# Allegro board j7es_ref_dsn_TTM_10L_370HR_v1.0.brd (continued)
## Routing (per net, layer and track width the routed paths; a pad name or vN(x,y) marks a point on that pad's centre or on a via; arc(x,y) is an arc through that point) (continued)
V3V3_DP0:
  vias: v1(129.16,14.94) v1(129.16,14.05) v1(129.16,13.16) v1(129.16,12.27)
VBAT:
  vias: v2(155.96,13.45)
VBAT_A:
  vias: v2(156.84,40.25) v2(156.84,39.11) v2(156.84,37.96) v2(156.84,36.82) v2(157.86,36.82) v2(158.88,36.82) v2(159.89,36.82) v2(160.78,36.82) v2(161.42,37.71) v2(161.8,38.85)
VBAT_F: length 2.3
  TOP w0.305: R1037.1 165.48,49.14 164.92,48.58 D1008.2
  vias: v2(164.47,73.14) v2(164.47,72.25) v2(164.47,71.36) v2(164.47,70.47) v2(167.89,70.47) v2(168.78,70.47) v2(169.67,70.47) v2(170.56,70.47)
VBAT_PM: length 15.6
  TOP w0.508: 159.51,16.26 159.51,17.13 ; 159.51,17.13 160.05,17.13 ; 159.51,17.13 158.98,17.13 ; 159.51,17.13 159.51,18.01 ; 155.33,17.64 C1023.1 ; C1023.1 156.83,17.64 ; C1023.1 156.08,17.02 ; R1012.2 158.12,15.78 ; R1012.2 156.35,15.15 ; R1012.2 159.88,15.15 ; 160.78,16.26 Q1002.3 ; Q1002.3 160.25,17.13 ; Q1002.3 160.78,18.01 ; Q1002.1 158.24,18.01 ; Q1002.1 158.78,17.13 ; Q1002.1 157.71,17.13 ; Q1002.1 158.24,16.26 ; 167.19,18.08 U1006.4 166.84,17.02
  vias: v2(149.22,16.5) v2(149.22,15.48) v2(149.22,14.47) v2(149.73,13.58) v2(150.62,13.58) v2(151.51,13.58) v2(152.4,13.58) v2(153.29,13.58) v2(153.8,16.5) v2(153.8,15.48) v2(153.8,14.47)
VBAT_SYS: length 11.5
  TOP w0.203: U1007.15 v2(192.28,98.42)
  TOP w0.305: v2(192.15,96.26) 191.64,96.26 191.21,96.69 C1028.1 191.21,96.84 191.64,97.27 v2(192.15,97.27) ; 36.2,29.58 v2(36.2,30.98)
  L4-SIGNAL w0.305: v2(192.15,97.27) 192.28,97.4 v2(192.28,98.42)
  BOTTOM w0.305: C2115.1 v2(36.2,30.98) RJ2008.1
  BOTTOM w0.508: v2(199.64,102.22) 199.52,102.1 R1142.2
  vias: v2(183.77,98.8) v2(183.77,97.91) v2(184.53,98.8) v2(184.53,97.91) v2(185.29,98.8) v2(185.29,97.91) v2(196.22,96.26)
VBUS_USBC_CONN: length 1.5
  TOP w0.305: v2(177.29,138.04) R1000.1
  BOTTOM w0.229: R171.1 v2(147.32,130.77)
  vias: v2(171.83,140.71) v2(171.83,139.82) v2(172.21,138.8) v2(172.21,137.78) v2(172.21,136.51) v2(172.21,135.37)
VCC_12V0:
  vias: v1(98.23,36.91) v1(98.23,35.99) v1(98.23,35.08) v1(99.15,36.91) v1(99.15,35.99) v1(99.15,35.08) v1(100.09,36.91) v1(100.09,35.99) v1(100.09,35.08)
VCC_12V_DSI0:
  vias: v1(99.69,6.63) v1(99.69,5.61) v1(99.69,4.6) v1(100.71,6.63) v1(100.71,5.61) v1(100.71,4.6) v1(101.6,6.63) v1(101.6,5.61) v1(101.6,4.6)
VCC_LM5141: length 7.7
  TOP w0.305: D1004.2 184.61,101.03 185.6,102.02 C1043.1 187.78,102.02 188.72,101.09 U1007.10
VCC_LM5175: length 24.1
  TOP w0.203: v2(168.4,48.63) 168.4,48.38 R1040.2
  TOP w0.305: U1008.23 172.76,61.5 v2(172.97,61.71) ; D1005.2 173.02,61.76 v2(172.97,61.71) ; v2(172.97,61.71) C1040.1 170.38,61.71 D1007.2
  BOTTOM w0.305: v2(172.97,61.71) 172.97,58.66 171.07,56.76 171.07,52.06 168.4,49.39 v2(168.4,48.63)
VCCA_3V3: length 15.8
  TOP w0.305: v1(81.28,104.67) U29.4 ; 126.49,99.68 126.53,99.65 U27.17 ; U29.10 v1(79.73,107.67) ; U29.54 78.7,101.63 78.74,101.59 ; U27.12 v1(129.07,100.7) ; U27.26 126.53,95.15 126.49,95.11 ; v1(133.07,102.22) U27.4 ; 78.74,111.24 78.7,111.21 U29.17 ; U29.35 71.68,106.67 ; U29.8 v1(79.73,106.67) ; U27.35 131.07,92.63 ; U27.8 v1(131.07,100.68) ; 74.17,101.59 74.2,101.63 U29.45 ; U27.54 136.11,99.65 136.14,99.68 ; 74.17,111.24 74.2,111.21 U29.26 ; U27.10 v1(130.07,100.68) ; U27.45 136.11,95.15 136.14,95.11 ; U29.12 v1(79.76,108.67)
  BOTTOM w0.305: v1(81.28,104.67) 81,104.38 C532.1 ; C481.1 133.35,101.94 v1(133.07,102.22)
  vias: v2(66.04,118.35) v2(66.04,117.34) v2(67.06,118.35) v2(67.06,117.34) v2(68.07,118.35) v2(68.07,117.34) v2(69.38,106.62) v2(69.38,105.98) v2(70.32,106.62) v2(70.32,105.98) v2(73.46,113.49) v2(73.46,112.55) v2(73.46,100.28) v2(73.46,99.34) v2(74.09,113.49) v2(74.09,112.55) v2(74.09,100.28) v2(74.09,99.34) v2(78.81,113.49) v2(78.81,112.55) v2(78.81,100.28) v2(78.81,99.34) v2(79.45,113.49) v2(79.45,112.55) v2(79.45,100.28) v2(79.45,99.34) v2(84.96,118.61) v2(84.96,117.59) v2(85.69,102.29) v2(85.98,118.61) v2(85.98,117.59) v2(86.21,101.69) v2(86.74,101.17) v2(87,118.61) v2(87,117.59) v2(87.95,106.95) v2(88.49,106.42) v2(89.01,105.86) v2(124.24,100.39) v2(124.24,99.76) v2(124.24,95.04) v2(124.24,94.4) v2(125.18,100.39) v2(125.18,99.76) v2(125.18,95.04) v2(125.18,94.4) v2(131.12,91.26) v2(131.12,90.32) v2(131.75,91.26) v2(131.75,90.32) v2(137.45,100.39) v2(137.45,99.76) v2(137.45,95.04) v2(137.45,94.4) v2(138.39,100.39) v2(138.39,99.76) v2(138.39,95.04) v2(138.39,94.4) v2(153.29,103.24) v2(153.29,101.97) v2(153.67,103.88) v2(153.67,102.61) v2(153.67,101.34) v2(154.05,103.24) v2(154.05,101.97) v2(154.43,103.88) v2(154.43,102.61) v2(154.43,101.34) v2(154.81,103.24) v2(154.81,101.97) v2(155.19,103.88) v2(155.19,102.61) v2(155.19,101.34) v2(155.57,103.24) v2(155.57,101.97) v2(155.96,103.88) v2(155.96,102.61) v2(155.96,101.34)
VDD1_LPDDR4_1V8: length 8.2
  TOP w0.305: v1(122.13,70.36) 122.53,70.03 U11.U12 ; U11.U1 131.33,70.03 v1(131.73,69.71) ; U11.G9 v1(124.53,63.86) ; C514.1 127.99,103.42 128.57,102.84 v1(128.57,102.1) U27.13 ; U11.T9 124.93,69.38 v1(124.53,69.06) ; U11.T4 128.93,69.38 v1(129.33,69.06) ; U11.F1 v1(131.73,63.21) ; U11.F12 v1(122.13,62.56) ; U11.G4 v1(128.53,63.86)
  BOTTOM w0.305: C341.1 121.94,70.17 v1(122.13,70.36) ; C345.1 131.81,69.79 v1(131.73,69.71)
  vias: v1(123.27,57.01) v1(125.17,76.06) v1(127.71,57.01) v1(128.35,76.06) v1(131.52,74.54) v1(134.03,58.28) v1(134.24,73.84)
VDD18_DSI: length 15
  TOP w0.305: v1(111.51,15.23) R3066.1 110.98,15.86 v1(109.56,17.28) ; R3065.1 v1(103.89,15.74)
  L2-SIGNAL w0.305: v1(109.56,17.28) 106.11,17.28 104.56,15.74 v1(103.89,15.74)
  BOTTOM w0.229: R3066.1 v1(111.51,15.23)
  BOTTOM w0.305: 108.83,17.28 v1(109.56,17.28) ; 108.83,17.28 U3019.24 ; 108.83,17.28 C3111.1 ; v1(110.94,29.76) 110.94,29.03 ; 110.94,29.03 C3100.1 ; 110.94,29.03 110.94,28.54 110.83,28.44 U3019.61
  vias: v1(112.01,34.28) v1(113.16,35.29) v1(114.81,34.66)
VDD_1P0: length 7
  TOP w0.305: C2086.1 44.78,29.25 C2087.1 ; C2086.1 46.23,28.4 46.35,28.27 R2059.2 R2058.2 ; C2086.1 46.43,29.45 L2017.2
VDD_CORE_0V8: length 100.9
  TOP w0.305: U9.K17 97.05,67.75 v1(96.65,67.35) ; U9.K11 v1(102.25,67.35) ; v1(97.45,73.75) 97.85,73.35 U9.U16 ; v1(98.25,72.15) 98.65,72.55 U9.T15 ; U9.N18 96.25,70.15 v1(95.85,69.75) ; v1(103.85,72.15) 103.45,72.55 U9.T9 ; v1(99.05,73.75) 99.45,73.35 U9.U14 ; 94.41,88.19 C66.3 ; U9.K15 98.65,67.75 v1(98.25,67.35) ; U9.V15 98.65,74.15 v1(98.25,74.55) ; U9.V20 94.65,74.15 v1(94.25,74.55) ; U9.L10 v1(103.05,68.15) ; U9.L18 96.25,68.55 v1(95.85,68.15) ; U9.T17 97.05,72.55 v1(96.65,72.15) ; U9.R16 97.85,71.75 v1(97.45,71.35) ; v1(94.25,71.35) 94.65,71.75 U9.R20 ; v1(98.25,70.55) 98.65,70.95 U9.P15 ; v1(99.85,71.35) 99.45,71.75 U9.R14 ; U9.W14 99.45,74.95 v1(99.05,75.35) ; U9.K9 v1(103.85,67.35) ; v2(75.92,111.47) 75.92,111.39 76.2,111.11 U29.22 ; U9.L16 97.85,68.55 v1(97.45,68.15) ; U9.R18 96.25,71.75 v1(95.85,71.35) ; U9.N16 97.85,70.15 v1(97.45,69.75) ; U9.P17 97.05,70.95 v1(96.65,70.55) ; U9.J10 v1(103.05,66.55) ; U9.P13 100.25,70.95 v1(100.65,70.55) ; U9.N14 v1(99.85,69.75) ; U9.M15 98.65,69.35 v1(98.25,68.95) ; U9.K13 v1(100.65,67.35) ; U9.V17 v1(96.65,74.55) ; U9.U18 v1(95.85,73.75)
  L6-PWR/GND w0.152: v1(94.25,71.35) 93.85,70.95 93.85,70.35 93.65,70.14 86.87,70.14 86.08,70.93 84.83,70.93 81.63,74.13 77.11,74.13 73.63,77.61 73.63,97.93 72.42,99.15 72.42,103.34 72.42,103.34 72.42,107.88 72.42,107.88 72.42,108.45 72.42,108.45 72.42,109.36 73.81,110.76 75.34,110.76 75.62,111.04 75.62,111.16 v2(75.92,111.47)
  BOTTOM w0.152: C318.1 103.88,72.13 v1(103.85,72.15)
  BOTTOM w0.203: C292.1 99.05,75.35 v1(99.05,75.35) ; C336.1 96.55,70.41 96.25,70.11 96.22,70.11 v1(95.85,69.75) ; v1(98.25,68.95) 98.25,68.97 97.87,69.35 97.81,69.35 97.51,69.65 C342.1 ; v1(96.65,70.55) 95.99,71.21 C330.1 ; v1(95.85,71.35) 96.15,71.65 96.15,71.67 96.55,72.06 C322.1 ; v1(96.65,67.35) 96.3,67.7 96.29,67.7 95.99,68 C361.1 ; C335.1 98.07,70.37 v1(97.45,69.75)
  BOTTOM w0.305: v1(97.45,68.15) 97.84,68.54 97.92,68.54 98.2,68.82 C353.1 ; C340.1 C352.1 ; v1(97.45,69.75) v1(96.65,70.55) 96.65,70.55 v1(97.45,71.35) 97.45,71.29 97.79,70.95 97.84,70.95 v1(98.25,70.55) ; C328.1 100.04,71.35 v1(99.85,71.35) v1(99.85,72.15) ; v1(102.25,67.35) v1(103.05,68.15) v1(103.85,67.35) ; v1(95.85,73.75) v1(96.65,74.55) 96.67,74.55 97.17,74.04 97.17,74.02 v1(97.45,73.75) v1(98.25,74.55) 98.59,74.89 98.59,74.89 v1(99.05,75.35) ; v1(103.05,66.55) 103.05,66.66 103.28,66.89 103.38,66.89 103.66,67.17 C364.1
  vias: v1(77.43,85.59) v1(77.43,81.78) v1(79.03,85.59) v1(79.03,81.78) v1(81.03,78.86) v1(81.03,75.43) v1(81.99,85.59) v1(81.99,81.78) v1(82.03,78.86) v1(82.03,75.43) v1(83.36,78.91) v1(83.36,75.43) v1(84.07,88.3) v1(84.36,75.43) v1(84.41,85.61) v1(84.48,78.91) v1(84.53,81.78) v1(85.34,88.3) v1(85.98,93.37) v1(85.98,91.77) v1(86.61,88.3) v1(87.88,88.3) v1(88.52,93.37) v1(88.52,91.77) v1(90.88,91.42) v1(90.88,90.37) v1(90.93,89.26) v1(90.93,88.26) v1(93.22,84.62) v1(94.35,91.42) v1(94.37,90.41) v1(94.34,89.29) v1(94.36,88.25) v2(65.79,93.72) v2(66.67,93.72) v2(68.2,93.72) v2(69.22,93.72) v2(71.5,117.46) v2(71.5,116.32) v2(71.5,115.18) v2(71.5,97.65) v2(71.5,96.51) v2(71.5,95.37) v2(72.39,117.46) v2(72.39,116.32) v2(72.39,115.18) v2(72.39,97.65) v2(72.39,96.51) v2(72.39,95.37) v2(75.31,119.62) v2(75.31,118.61) v2(75.31,94.22) v2(75.31,93.21) v2(76.45,119.62) v2(76.45,118.61) v2(76.45,94.22) v2(76.45,93.21) v2(77.6,119.62) v2(77.6,118.61) v2(77.6,94.22) v2(77.6,93.21) v2(80.52,117.46) v2(80.52,116.32) v2(80.52,115.18) v2(80.52,97.65) v2(80.52,96.51) v2(80.52,95.37) v2(81.41,117.46) v2(81.41,116.32) v2(81.41,115.18) v2(81.41,97.65) v2(81.41,96.51) v2(81.41,95.37) v2(84.71,94.86) v2(85.72,94.86) v2(87.12,94.86) v2(88.14,94.86) v2(93.65,97.65) v2(93.65,96.89) v2(93.65,96.26) v2(96.39,42.53) v2(103.63,94.22) v2(107.82,42.53)
VDD_CORE_RAM_0V85: length 2.3
  TOP w0.305: U9.V16 97.85,74.15 v1(97.45,74.55) ; v1(100.65,74.55) 100.25,74.15 U9.V13 ; U9.L14 v1(99.85,68.15) ; U9.W19 v1(95.05,75.35)
  vias: v2(72.52,78.35) v2(77.34,79.62)
VDD_CPU_AVS: length 85.9
  TOP w0.305: U9.N10 102.65,70.14 v1(103.05,69.74) ; U9.N10 v1(102.25,70.55) 101.85,70.95 U9.P11 101.85,70.94 v1(102.25,71.34) ; U9.N10 v1(102.25,69.74) ; v1(103.05,71.35) 102.65,71.75 U9.R10 102.65,71.74 v1(102.25,72.14) ; v1(101.45,72.14) 101.05,71.75 U9.R12 101.05,71.74 v1(100.65,72.14) ; U9.V9 103.45,74.15 v1(103.85,74.55) ; U9.U10 102.65,73.35 v1(103.05,73.75) ; v1(102.25,74.55) 101.85,74.15 U9.V11 ; U27.22 126.62,97.15 126.34,96.87 v2(126.26,96.87) ; v1(103.05,75.35) 102.65,74.95 U9.W10
  L4-SIGNAL w0.152: v2(126.26,96.87) 126.77,96.87 127.25,96.38 127.25,94.22 128.02,93.46 136.02,93.46 137.03,92.45 137.03,87.54 135.2,85.71 135.2,79.53 132.83,77.16 111.84,77.16 110.42,75.74 109.29,75.74 109.29,75.74 108.49,75.74 108.26,75.51 108.26,75.23 108.25,75.22 108.25,75.18 108.02,74.95 107.98,74.95 107.97,74.94 107.69,74.94 107.46,74.71 107.46,74.43 107.46,74.43 107.46,74.35 107.26,74.16 106.88,74.16 106.65,73.93 106.65,73.37 106.55,73.27 104.44,73.27 104.25,73.47 104.25,74.16 v1(103.85,74.55)
  BOTTOM w0.305: v1(103.05,71.35) 102.26,71.35 v1(102.25,71.34) ; 102.23,73.73 102.23,73.68 102.31,73.75 v1(103.05,73.75) ; C69.3 100.66,72.15 ; 100.66,72.15 v1(100.65,72.14) ; 100.66,72.15 100.74,72.23 C351.1 102.17,72.23 v1(102.25,72.14) ; C69.1 100.66,73.75 v1(100.66,73.75) v1(101.45,73.75) 101.47,73.76 102.24,73.76 v1(102.25,73.75) 102.25,74.46 102.23,74.54 C304.1 ; v1(102.25,72.14) 102.52,72.4 C68.1 ; v1(102.25,72.14) 102.25,72.14 v1(102.25,71.34) ; v1(102.25,71.34) v1(102.25,70.55) v1(102.25,69.74) v1(103.05,69.74) ; C68.3 103.22,73.68 C308.1 ; v1(103.85,74.55) 103.17,73.87 C308.1 ; 103.15,73.75 C308.1 ; C298.1 103.75,74.64 103.12,75.27 C294.1 102.67,74.95 102.62,74.95 102.25,74.59 v1(102.25,74.55)
  vias: v1(107.24,88.3) v1(109.02,88.3) v1(110.87,88.3) v1(112.65,89.4) v1(112.65,88.15) v1(115.36,86.22) v1(115.36,84.32) v1(115.36,82.41) v1(117.35,86.22) v1(117.35,84.32) v1(118.36,86.22) v1(118.36,84.32) v1(119.47,86.22) v1(119.47,84.32) v1(119.47,82.41) v1(121.07,86.22) v1(121.07,84.32) v1(121.07,82.41) v1(122.26,86.22) v1(123.86,86.22) v2(118.62,104.38) v2(119.63,104.38) v2(120.27,102.35) v2(120.27,101.46) v2(120.27,93.33) v2(120.27,92.45) v2(121.03,104.38) v2(121.41,102.35) v2(121.41,101.46) v2(121.41,93.33) v2(121.41,92.45) v2(122.05,104.38) v2(122.55,102.35) v2(122.55,101.46) v2(122.55,93.33) v2(122.55,92.45) v2(123.88,83.2) v2(124.89,83.2) v2(126.36,83.23) v2(127.38,83.23)
VDD_CPU_RAM_0V85: length 1.1
  TOP w0.305: U9.L11 v1(102.25,68.15) ; v1(101.45,75.35) 101.05,74.95 U9.W12
  vias: v2(90.94,103.75) v2(92.2,99.3)
VDD_DDR_1V1: length 84.7
  TOP w0.089: 126.06,69.71 124.45,69.71 U11.U10 123.8,69.71 123.06,69.71
  TOP w0.102: U11.F8 125.4,63.21 124.45,63.21 U11.F10
  TOP w0.203: U11.H12 122.29,63.95 121.95,63.95 121.68,64.22 121.68,64.72 v1(122.1,65.14)
  TOP w0.229: U9.T1 109.86,72.54 ; U11.F10 123.83,63.19 123.83,63.24 ; v1(136.14,97.65) 136.14,97.65 U27.50
  TOP w0.305: U11.B10 124.05,60.28 123.7,59.93 ; U11.N10 124.13,67.43 v1(124.53,67.76) ; U11.F3 v1(130.13,62.56) ; U9.N8 v1(104.65,69.75) ; U11.R12 122.53,68.73 v1(122.13,68.41) ; U11.D8 125.73,61.58 126.11,61.2 ; U9.R6 105.85,71.75 v1(106.25,71.35) ; U11.F8 v1(126.13,62.56) ; v1(129.33,59.96) 128.93,59.63 U11.A4 ; U9.G8 104.25,65.35 U9.G8 ; U9.G8 v1(104.65,64.95) ; U11.W1 132.54,71.33 v1(132.59,71.28) ; U9.P7 105.05,70.95 v1(105.45,70.55) ; v1(127.73,69.71) 128.13,70.03 U11.U5 ; U9.J6 105.85,66.95 v1(106.25,66.55) ; U11.N3 129.73,67.43 v1(129.33,67.76) ; 122.3,61.33 122.53,61.56 U11.D12 122.53,61.61 122.3,61.84 ; v1(127.73,69.06) 128.13,68.73 U11.R5 ; 109.86,72.55 U9.T1 109.85,72.55 ; v1(122.65,66.56) 122.53,66.69 U11.N12 ; U11.W5 127.67,71.33 ; v1(105.45,68.95) 105.05,69.35 U9.M7 ; v1(131.73,65.81) U11.K1 ; 127.76,59.93 128.11,60.28 U11.B5 ; U11.H1 v1(131.73,64.51) ; U11.B3 v1(130.13,60.61) ; U11.K12 122.12,65.15 122.1,65.14 v1(122.1,65.14) ; U11.H5 v1(127.73,63.86) ; U11.AB9 124.93,73.28 125.18,73.54 v1(125.18,73.76) ; U9.K7 v1(105.45,67.35) ; U9.R8 104.25,71.75 v1(104.65,71.35) ; 127.76,73.01 128.13,72.65 U11.AA5 ; v1(130.13,72.31) 129.73,72.63 U11.AA3 ; U9.L8 v1(104.65,68.15) ; v1(105.45,72.15) 105.05,72.55 U9.T7 ; U11.B8 126.01,60.57 ; U11.R1 131.33,68.73 v1(131.73,68.41) ; U11.AA8 126.11,73.01 ; U11.W8 126.21,71.33 ; U11.F5 v1(127.73,62.56) ; U11.U8 125.73,70.03 v1(126.13,70.36) ; U9.A1 v1(110.25,60.14) ; v1(104.65,66.55) 104.25,66.95 U9.J8 ; U11.W12 121.95,71.33 ; v1(125.33,59.96) 125.32,59.96 124.94,59.64 124.93,59.63 U11.A9 ; 132.54,61.58 v1(132.59,61.54) ; U11.H8 v1(126.13,63.86) ; v1(126.13,69.06) 125.73,68.73 U11.R8 ; v1(131.73,67.11) 131.33,67.43 U11.N1 ; v1(130.13,70.36) 129.73,70.03 U11.U3 ; 131.57,61.33 131.33,61.57 U11.D1 131.33,61.59 131.57,61.84 ; v1(124.53,65.16) U11.K10 ; U11.AB4 v1(128.93,73.82) ; U11.AA10 123.75,73.01 ; 109.86,72.54 v1(110.25,72.15) ; U9.M9 v1(103.85,68.95) ; v1(129.33,65.16) U11.K3 ; U9.H7 v1(105.45,65.75) ; U11.D5 127.64,61.58
  L4-SIGNAL w0.152: v1(136.14,97.65) 135.64,97.65 135.38,97.4 135.38,95.11 137.69,92.8 137.69,87.38 135.79,85.47 135.79,79.25 133.35,76.81 133.35,70.03 v1(131.73,68.41)
  BOTTOM w0.229: v1(110.25,72.15) 110.28,72.13 C317.1 ; R180.1 v1(120.69,88.35)
  BOTTOM w0.305: v1(110.25,60.14) 110.54,60.43 110.83,60.72 110.92,60.72 C390.1 ; v1(125.18,73.76) 125.27,73.85 C303.1 ; R242.1 127.89,58.64 126.75,58.64 R243.1 v1(126.75,58) ; v1(132.59,66.92) 132.67,67 C374.1 ; C384.1 122.02,65.22 v1(122.1,65.14) ; v1(128.93,73.82) 128.98,73.88 C302.1 ; R232.1 119.29,67.57 119.53,67.81 119.53,68.52 119.63,68.62 v2(119.91,68.9) ; C393.1 125.05,59.68 v1(125.33,59.96) ; v1(129.33,59.96) 129.33,59.95 C392.1
  vias: v1(112.66,58.03) v1(113.66,58.03) v1(114.17,54.97) v1(114.17,53.96) v1(115.36,70.6) v1(115.36,68.06) v1(115.36,61.71) v1(115.32,58.03) v1(115.95,54.97) v1(115.95,53.96) v1(116.33,58.03) v1(117.73,55.27) v1(117.73,53.67) v1(121.46,55.49) v1(122.6,77.97) v1(123.01,76.06) v1(123.62,55.49) v1(124.64,77.97) v1(125.55,57.01) v1(125.78,55.49) v1(126.67,77.97) v1(126.93,63.16) v1(128.06,55.49) v1(128.7,77.97) v1(130.13,57.01) v1(130.35,55.49) v1(131.25,66.33) v1(131.52,76.06) v1(132.13,59.35) v1(132.79,58.28) v1(132.84,56.75) v1(132.84,55.74) v1(134.24,71.05) v1(134.75,56.75) v1(134.75,55.74) v1(134.87,67) v1(134.87,63.82) v1(134.87,60.65) v1(135.38,75.93) v1(135.38,74.92) v1(136.09,68.91) v1(136.52,60.65) v1(136.65,58.45) v1(136.65,56.85) v1(137.29,74.02) v1(137.29,73.01) v1(137.29,70.93) v1(137.26,61.85) v1(139.06,72.38) v1(139.06,71.36) v1(139.06,70.35) v1(140.21,72.38) v1(140.21,71.36) v1(140.21,70.35) v2(140.08,102.35) v2(140.08,101.46) v2(141.22,102.35) v2(141.22,101.46) v2(142.37,102.35) v2(142.37,101.46)
VDD_DSI_OSC: length 6.4
  BOTTOM w0.229: 100.73,17.93 C3108.2 100.76,18.45 100.97,18.66 U3020.4
  BOTTOM w0.305: 100.71,17.3 100.73,17.32 ; 100.73,17.93 99.82,17.93 99.42,18.34 U3020.1
  BOTTOM w0.381: 100.71,17.3 100.46,17.04 FL3026.3 ; 100.73,17.32 100.73,17.93
VDD_IO_1V8: length 35.9
  TOP w0.305: U9.AA8 104.25,76.55 v1(104.65,76.95) 104.66,76.95 U9.AB7 105.05,77.35 v1(105.45,77.75) ; U1017.H8 v2(154.66,82.2) ; U1017.P8 v2(147.66,82.2) ; v1(120.36,34.57) 119.63,34.57 v1(119.63,33.88) ; C544.1 81.85,107.05 81.73,107.17 v1(81.15,107.17) U29.9 ; U1017.L4 v2(150.66,87.21) ; U1017.P3 v2(147.66,88.21) ; U1017.L2 v2(150.66,89.21) ; C260.1 v1(102.13,92.95) ; U1017.L7 v2(150.66,83.21) ; U9.Y7 105.05,75.75 v1(105.45,76.15) ; U1017.H3 v2(154.66,88.21) ; U1017.L9 v2(150.66,81.2)
  L6-PWR/GND w0.305: v2(108.58,97.65) v2(108.58,96.76) v2(108.58,95.87) 106.93,95.87 104.01,92.95 v1(102.13,92.95)
  BOTTOM w0.305: R1198.1 R1191.1 150.62,81.17 v2(150.66,81.2) ; v2(147.66,82.2) 147.45,82.41 C1249.1 ; R1189.1 v2(152.65,88.25) R1188.1 ; 151.38,85.97 151.38,86.48 v2(150.66,87.21) ; v2(146.43,83.43) 146.1,83.43 145.8,83.73 145.8,84.19 ; v2(150.66,89.21) 149.84,90.03 R1197.1 ; v2(150.66,83.21) 150.5,83.05 R1196.1 ; v2(147.66,88.21) 147.7,88.17 R1201.1 ; v2(154.66,82.2) 154.45,82.41 C1242.1 ; v2(152.65,84.19) 152.53,84.06 R1190.1 ; R1200.1 v2(148.72,84.19)
  vias: v1(102.13,91.68) v1(102.11,90.41) v1(102.11,89.14)
VDD_IO_3V3: length 59.8
  TOP w0.305: U9.AC20 94.65,78.15 v1(94.25,78.55) ; R1001.2 v2(168.02,134.23) ; v1(92.65,73.75) 93.05,73.35 U9.U22 ; U9.AC19 95.46,78.15 v1(95.06,78.55) ; R79.1 v2(40.89,71.87) ; U1017.F7 v2(156.66,83.21) ; R23.1 v2(142.88,82.92) ; U9.AA21 v1(93.45,76.95) ; U1017.F9 v2(156.66,81.2) ; R81.1 v2(40.89,74.41) ; v2(114.73,116.65) R20.1 R25.1 ; v1(96.65,78.55) 97.05,78.15 U9.AC17 ; 36.2,35.17 v2(36.2,36.57) ; R38.1 R37.1 v2(104.98,25.59) ; v1(94.26,73.75) 94.66,73.35 U9.U20 ; U9.AA17 97.05,76.55 v1(96.65,76.95) ; R43.2 v2(55.45,89.73) ; U9.W22 93.05,74.95 v1(92.65,75.35) ; U9.AA20 94.66,76.55 v1(94.26,76.95) ; v1(97.45,77.75) 97.85,77.35 U9.AB16 ; C1209.2 v2(137.29,147.44) U1011.8 ; v1(104.65,73.75) 104.25,73.35 U9.U8 ; RJ1000.1 v2(176.47,134.36) ; v2(49.4,34.79) R2020.1 R2021.1 ; C2084.1 v2(55.75,31.36) ; R27.1 v2(148.46,76.7) ; R86.1 v2(55.63,70.09) ; U1017.F8 v2(156.66,82.2) ; U9.V21 93.86,74.15 v1(93.46,74.55) ; R1002.2 v2(168.02,133.09) ; U1017.F5 v2(156.66,86.21) ; L2004.2 v2(43.69,33.14) ; U9.V7 105.05,74.15 v1(105.45,74.55) ; U1017.F2 v2(156.66,89.21) ; R66.1 R54.1 v2(156.08,76.82) ; U1017.F6 v2(156.66,84.21) ; U1002.9 158.81,126.16 v2(158.62,125.97) ; U2023.3 v2(52.2,29.07) ; U9.Y22 93.05,75.75 v1(92.65,76.15) ; R3061.2 v2(128.23,19.51) ; U2023.4 v2(54.23,29.07) ; U9.AA19 v1(95.05,76.95) ; U9.AB18 96.25,77.35 v1(95.85,77.75) ; L2008.1 v2(38.35,48.38) ; U2023.6 v2(54.23,31.36) ; U1017.F3 v2(156.66,88.21) ; U1017.F4 v2(156.66,87.21)
  BOTTOM w0.305: v2(156.66,81.2) 156.84,81.02 C1240.1 ; v2(47.37,54.57) 47.37,54.73 R1219.1 ; 102.84,18.9 103.46,19.52 U3019.33 ; R2099.1 v2(32.38,28.44) ; R2116.2 v2(51.56,46.94) ; C1241.1 156.84,86.03 v2(156.66,86.21) ; U1033.5 148.74,94.6 148.46,94.88 v2(148.46,95.49) ; R2111.1 v2(51.18,48.76) ; v2(115.95,20.31) 116.2,20.06 C3105.1 ; v2(158.62,125.97) C1198.1 ; R2114.2 R2113.2 R2112.2 v2(43.31,43.68) ; R1134.1 v2(157.92,129.28) ; R3114.1 v2(105.72,15.56) ; v2(36.2,36.57) C2120.1 ; C3106.1 115.06,19.52 U3019.16
  BOTTOM w0.381: 115.06,19.52 116.2,19.52 C3105.1 ; v1(102.08,18.9) 102.84,18.9 C3107.1
  BOTTOM w0.508: C1245.2 v2(148.46,95.49)
  vias: v1(94.41,93.73) v1(94.41,92.62) v1(94.87,86.6) v1(94.87,84.57) v1(96.01,17.93) v1(96.01,16.15) v1(96.27,86.6) v1(96.27,84.57) v1(97.41,17.93) v1(97.41,16.15) v1(97.66,86.65) v1(97.66,84.57) v1(99.06,97.78) v1(99.06,96.93) v1(99.06,95.33) v1(99.05,94.14) v1(99.05,93.04) v1(99.1,91.96) v1(99.1,90.9) v1(99.05,89.82) v1(99.05,88.74) v1(99.06,86.52) v1(99.06,84.54) v1(99.69,97.4) v1(100.58,86.52) v1(100.58,84.49) v1(101.98,86.52) v1(101.98,84.57) v1(103.38,86.6) v1(103.38,84.57) v1(104.78,86.6) v1(104.78,84.57) v1(106.17,86.6) v2(151.26,108.32) v2(152.02,108.32) v2(152.02,61.2) v2(152.02,60.06) v2(153.29,61.2)
VDD_MCU_0V85: length 155.8
  TOP w0.229: U27.49 135.89,97.15 136.02,97.02 v1(136.05,97.02)
  TOP w0.305: v1(93.45,68.95) 93.85,69.35 U9.M21 ; U9.L20 94.65,68.55 v1(94.25,68.15) ; v1(95.05,70.55) 95.45,70.95 U9.P19 ; v1(94.25,69.75) 94.65,70.15 U9.N20 ; FL9.1 v2(88.14,42.66) ; U9.M19 95.45,69.35 v1(95.05,68.95)
  TOP w0.381: 87.63,51.21 C184.3 v1(86.61,52.31) ; 87.63,51.21 89.41,51.21 ; 87.63,51.21 87.63,53.7 ; 87.63,51.21 87.63,49.61 ; 89.41,51.21 89.41,49.61 ; 89.41,51.21 89.41,53.7 ; 89.41,51.21 90.12,51.21 v1(90.42,50.91) v1(90.42,52.06) ; 87.63,53.7 87.63,55.31 ; 87.63,53.7 86.99,53.7 v1(86.61,53.32) ; 87.63,53.7 89.41,53.7 ; 89.41,53.7 89.41,55.31 ; 89.41,53.7 89.79,53.7 v1(90.42,53.07)
  TOP w0.508: C160.1 v1(90.42,52.06) ; C198.1 v1(86.61,52.31) ; v1(90.42,55.31) v1(88.52,55.31) v1(86.61,55.31) ; 90.42,49.9 90.12,49.61 v1(86.61,49.61)
  L4-SIGNAL w0.152: v2(139.7,91.43) 139.19,91.94 139.19,97.14 138.94,97.4 137.16,97.4 136.78,97.02 v1(136.05,97.02)
  L6-PWR/GND w0.102: v1(95.05,70.55) 95.09,70.55 95.5,70.96 97,70.96 97.05,70.91 97.05,68.77 97.28,68.54 97.61,68.54 97.84,68.32 97.84,48.58 100.58,45.84 102.11,45.84 103.5,47.23 103.5,49.39 105.54,51.42 121.54,51.42 123.7,53.58 134.62,53.58 141.35,60.31 141.35,76.95 138.43,79.87 138.43,90.16 v2(139.7,91.43)
  BOTTOM w0.305: v1(94.25,68.15) 93.91,68.48 93.91,68.48 93.57,68.82 C355.1 93.57,69.08 93.9,69.41 93.91,69.41 v1(94.25,69.75) ; C358.1 94.34,68.32 94.96,68.95 C354.1
  vias: v1(86.61,51.17) v1(90.42,49.9) v2(140.08,93.33) v2(140.08,92.45) v2(141.22,93.33) v2(141.22,92.45) v2(142.37,93.33) v2(142.37,92.45)
VDD_MCU_RAM_0V85: length 7
  TOP w0.305: U9.T19 95.45,72.55 v1(95.05,72.15) ; v1(95.05,67.35) 95.45,67.75 U9.K19
  TOP w0.381: 89.4,46.47 89.4,47.02 89.04,47.37 v1(88.46,47.37)
  TOP w0.508: FL9.2 89.7,42.84 C121.1 89.75,44.39 89.66,44.48 89.66,45.88 89.4,46.47 C130.1
VDD_MCUIO_1V8: length 24.1
  TOP w0.305: v2(70.87,42.66) C173.1 71.56,42.7 U18.5 ; v2(75.34,45.99) 76.01,45.99 R161.1 ; R151.1 R150.1 v2(84,44.06) ; C513.1 129.36,103.42 129.36,103.04 129.57,102.83 v1(129.57,102.1) U27.11 ; v1(95.05,65.75) 95.45,66.15 U9.H19 ; v1(93.45,65.75) 93.85,66.15 U9.H21 ; v2(84.02,45) 83.81,45.2 R149.1 83.26,45.24 83.26,45.84 82.96,46.14 R153.2 81.97,46.14 ; v2(75.34,44.62) 76.01,44.62 R162.1 ; R158.1 v2(76.82,42.6) ; 69.95,48.12 R114.2 69.34,48.12 v2(69.09,47.87) ; R156.1 v2(79.88,41.06) ; R154.1 v2(80.95,41.09) ; U9.J20 94.65,66.95 v1(94.25,66.55)
  BOTTOM w0.152: v1(94.23,58.23) 94.27,58.2 C396.1 ; C371.1 95.21,65.58 v1(95.05,65.75)
  BOTTOM w0.305: U24.B4 v2(78.75,46.46) ; R3139.2 R3138.2 v2(79.25,50.15) ; R3140.2 v2(81.28,50.15) ; U24.D1 81.29,44.96 81.51,44.75 82.19,44.75 82.44,45 C413.1 v2(84.02,45) ; U24.E4 v2(78.75,43.46)
  vias: v1(94.87,54.97) v1(94.87,53.96) v2(84.71,46.43)
VDD_MCUIO_3V3: length 26.4
  TOP w0.229: v1(76.2,103.16) 76.15,103.11 75.95,103.11 75.7,102.87 U29.48 ; v1(134.49,97.22) 134.49,96.89 134.74,96.65 U27.48
  TOP w0.305: U9.L22 93.05,68.55 v1(92.65,68.15) ; v2(72.16,47.59) 72.16,48.12 R115.2 ; R105.1 v2(69.09,57.27) ; v1(92.65,68.95) 93.05,69.35 U9.M22 ; R106.1 v2(69.09,60.44) ; U9.K21 93.84,67.74 v1(93.45,67.35) ; v1(92.65,66.55) 93.04,66.94 U9.J22 ; v2(133.22,84.55) 133.22,84.57 132.97,84.32 R3145.2 ; R74.1 v2(69.09,58.54) ; R121.1 v2(69.11,56.05)
  L2-SIGNAL w0.152: v1(134.49,97.22) 133.99,97.73 133.99,100.57 133.22,101.34 127.88,101.34 127.71,101.16 v2(127.25,101.16)
  BOTTOM w0.152: R273.2 v2(127.25,101.16)
  BOTTOM w0.305: v2(44.96,57.9) 45.21,57.65 R3143.1 ; v2(51.31,54.6) 51.31,54.6 R1208.1 ; v2(50.67,59.81) R1206.1 R1207.1 ; R1209.1 v2(50.67,57.27)
  vias: v1(81.03,70.6) v1(82.03,70.6) v2(59.69,99.81) v2(59.69,98.67)
VDD_PHYIO_1V8: length 45.2
  TOP w0.305: U9.W7 105.05,74.95 v1(105.45,75.35) ; U27.37 132.07,92.56 v1(131.95,92.45)
  L4-SIGNAL w0.152: v1(131.95,92.45) 131.52,92.01 130.12,92.01 129.51,91.4 120.03,91.4 117.86,93.57 117.86,93.81 117.86,93.81 117.86,101.84 112.85,106.85 102.31,106.85 101.78,106.32 101.78,105.24 102.04,104.98 v1(102.04,104.89)
  vias: v1(92.21,42.53) v1(101.48,42.53) v1(102.11,104.24) v1(108.33,104.38) v1(112.9,80.51) v2(130.81,89.02) v2(130.81,87.87) v2(130.81,86.73) v2(131.7,89.02) v2(131.7,87.87) v2(131.7,86.73) v2(139.7,82.79) v2(141.1,82.79)
VDD_PHYIO_1V8_REG_SW: length 1.6
  TOP w0.229: 130.57,91.81 U27.34
VDD_RAM_0V85: length 29.9
  TOP w0.305: v1(71.37,105.67) U29.37
  L6-PWR/GND w0.152: v1(71.67,80.13) 73.08,81.54 73.08,97.7 71.86,98.92 71.86,99.15 71.86,101.73 71.86,101.73 71.86,104.75 71.37,105.23 v1(71.37,105.67)
  BOTTOM w0.305: v1(71.67,80.13) 72.25,80.13 FL21.1 72.17,79.52 71.95,79.52 71.92,79.49 71.67,79.49 v1(71.67,79.47)
  vias: v2(65.79,106.92) v2(65.79,106.03) v2(66.93,106.92) v2(66.93,106.03) v2(68.07,106.92) v2(68.07,106.03) v2(93.34,102.99)
VDD_RAM_0V85_REG_SW: length 1.6
  TOP w0.229: 70.87,107.17 U29.34
VDD_SD_DV: length 12.6
  TOP w0.305: C546.1 81.9,109.17 v1(81.15,109.17) U29.13 ; v1(92.65,72.15) 93.05,72.55 U9.T22 ; v1(94.25,72.15) 94.65,72.55 U9.T20
  L4-SIGNAL w0.305: 92.65,72.15 92.65,72.16 92.1,72.71 86.46,72.71 85.9,72.15 ; 92.65,72.15 93.15,72.66 93.74,72.66 v1(94.25,72.15) ; 92.65,72.15 v1(92.65,72.15)
  vias: v1(78.65,70.6)
VDDA_0P8_CSIRX: length 7.2
  TOP w0.305: v1(96.65,65.75) 97.05,66.15 U9.H17
  BOTTOM w0.203: C446.1 96.65,65.66 v1(96.65,65.75)
  BOTTOM w0.305: v1(96.52,47.87) 96.87,47.52 97.12,47.52 97.49,47.15 C404.1
  BOTTOM w0.508: 97.88,44.39 97.79,44.48 97.79,45.38 97.49,45.68 C404.1 ; 97.88,44.39 97.79,44.3 97.79,42.53 FL27.2 ; 97.88,44.39 97.83,44.44 C405.1
VDDA_0P8_DLL_MMC0: length 27.4
  TOP w0.305: U9.Y9 103.45,75.75 v1(103.85,76.15)
  TOP w0.381: C49.1 113.21,92.27 113.61,91.87 v1(114.17,91.87)
  TOP w0.508: FL6.2 112.86,96.21 112.86,94.22 ; 112.86,94.22 C50.1 ; 112.86,94.22 112.86,93.46 113.21,93.12 C49.1
  L7-SIGNAL w0.152: 110.11,83.17 109.85,82.91 109.85,82.39 109.6,82.14 109.29,82.14 109.06,81.91 109.06,81.51 108.89,81.34 108.49,81.34 108.26,81.11 108.26,80.82 108.25,80.8 108.25,80.79 108.02,80.56 108,80.56 107.97,80.53 107.69,80.53 107.47,80.31 107.47,80.03 107.17,79.73 106.9,79.73 106.67,79.51 106.67,78.43 106.41,78.17 105.33,78.17 105.07,77.91 105.07,77.63 104.77,77.33 104.49,77.33 104.27,77.11 104.27,76.57 v1(103.85,76.15)
  L7-SIGNAL w0.305: v1(114.17,91.87) 114.17,91.37 113.66,90.86 113.66,86.73 110.11,83.17
VDDA_0P8_DP: length 6
  TOP w0.305: U9.J12 101.05,66.95 v1(101.45,66.55) ; v1(101.45,64.95) 101.05,65.35 U9.G12
  BOTTOM w0.381: v1(108.84,47.11) 109.04,46.9 C402.1 109.04,44.78 C403.1 109.39,43.38 109.34,43.33 FL26.2
VDDA_0P8_DP_C: length 5.7
  TOP w0.305: U9.H13 v1(100.65,65.75) ; U9.G14 99.45,65.34 v1(99.85,64.94)
  TOP w0.381: C190.1 v2(109.73,46.34)
  TOP w0.508: C190.1 109.04,45.88 109.39,45.54 C189.1 109.41,44.41 FL13.2
VDDA_0P8_DSITX: length 6.9
  TOP w0.305: v1(97.45,66.55) 97.85,66.95 U9.J16 ; U9.H15 98.65,66.15 v1(98.25,65.75)
  TOP w0.381: C188.1 97.49,46.73 97.11,47.11 v1(96.52,47.11)
  TOP w0.508: 97.88,44.39 97.79,44.3 97.79,43.55 97.93,43.41 FL12.2 ; 97.88,44.39 97.83,44.44 C187.1 ; 97.88,44.39 97.93,44.44 97.93,45.9 C188.1
VDDA_0P8_PLL_DDR: length 0.6
  TOP w0.305: U9.N9 v1(103.85,69.75)
  vias: v1(122.68,49.29) v1(122.68,48.63)
VDDA_0P8_PLL_MLB: length 36.9
  TOP w0.305: U9.W8 104.25,74.95 v1(104.65,75.35)
  L6-PWR/GND w0.102: 106.51,74.95 105.05,74.95 v1(104.65,75.35) 105.05,75.75 106.43,75.75 ; 106.43,75.75 106.43,75.75 106.62,75.55 ; 106.43,75.75 106.87,75.75 ; 107.44,75.17 107.44,75.55 107.25,75.75 106.87,75.75 ; 106.87,75.75 106.68,75.55
  L7-SIGNAL w0.152: 110.74,81.52 110.59,81.37 110.13,81.37 109.83,81.07 109.83,80.79 109.61,80.57 109.33,80.57 109.03,80.27 109.03,79.99 108.81,79.77 108.53,79.77 108.27,79.51 108.27,79.23 108.01,78.97 107.73,78.97 107.47,78.71 107.47,78.43 107.21,78.17 106.93,78.17 106.67,77.91 106.67,77.63 106.41,77.37 106.13,77.37 105.87,77.11 105.87,76.83 105.61,76.57 105.33,76.57 105.07,76.31 105.07,75.77 v1(104.65,75.35)
  L7-SIGNAL w0.305: 110.74,81.52 111.06,81.84 111.06,83.36 115.82,88.13 115.82,89.65 115.19,90.29 115.19,97.24 v2(113.52,98.9)
VDDA_0P8_SERDES: length 3.4
  TOP w0.305: U9.AA15 98.65,76.55 v1(98.25,76.95) ; v1(99.05,76.15) 99.45,75.75 U9.Y14 ; U9.Y11 101.85,75.75 v1(102.25,76.15) ; v1(101.45,76.95) 101.05,76.55 U9.AA12 ; v1(97.45,76.15) 97.85,75.75 U9.Y16 ; v1(100.65,76.15) 100.25,75.75 U9.Y13
  vias: v2(89.79,92.45) v2(90.55,92.45)
VDDA_0P8_SERDES_C: length 2.3
  TOP w0.305: U9.AB14 99.45,77.35 v1(99.05,77.75) ; v1(98.25,77.75) 98.65,77.35 U9.AB15 ; U9.AB13 100.25,77.35 v1(100.65,77.75) ; U9.AB12 101.05,77.35 v1(101.45,77.75)
  vias: v2(91.57,92.57)
VDDA_0P8_UFS: length 22.1
  TOP w0.305: U9.AB9 103.45,77.35 v1(103.85,77.75)
  L4-SIGNAL w0.152: 106.66,83.81 106.66,80.8 106.65,80.79 106.65,79.99 106.4,79.74 106.09,79.74 105.86,79.51 105.86,79.18 105.62,78.94 105.29,78.94 105.06,78.71 105.06,78.38 104.81,78.13 104.23,78.13 v1(103.85,77.75)
  L4-SIGNAL w0.305: 106.66,83.81 106.66,84.04 107.95,85.33 107.95,90.39 108.08,90.52 v1(108.08,91.18)
  BOTTOM w0.381: C243.1 107.11,91.61 107.54,91.18 v1(108.08,91.18)
  BOTTOM w0.508: C243.1 107.11,92.93 106.81,93.23 C242.1 105.27,94.22 FL18.2
VDDA_0P8_USB: length 24.4
  TOP w0.305: v1(103.05,76.95) 102.65,76.55 U9.AA10
  TOP w0.381: C47.1 107.09,92.57 107.09,92.29 107.57,91.81 v1(108.08,91.81)
  TOP w0.508: FL5.2 C48.1 106.81,92.86 107.09,92.57
  L4-SIGNAL w0.152: 107.45,83.94 107.45,83.19 107.44,83.18 107.44,82.72 107.45,82.71 107.45,82.39 107.44,82.38 107.44,81.92 107.45,81.91 107.45,81.59 107.44,81.58 107.44,81.12 107.45,81.11 107.45,80.79 107.44,80.78 107.44,80.32 107.45,80.31 107.45,79.99 107.22,79.76 107.2,79.76 107.19,79.74 106.89,79.74 106.66,79.51 106.66,79.22 106.65,79.2 106.65,79.19 106.42,78.96 106.4,78.96 106.39,78.94 106.09,78.94 105.86,78.71 105.86,78.42 105.85,78.4 105.85,78.39 105.62,78.16 105.32,78.16 105.31,78.14 105.29,78.14 105.06,77.91 105.06,77.62 104.81,77.37 103.47,77.37 v1(103.05,76.95)
  L4-SIGNAL w0.305: 107.45,83.94 108.46,84.95 108.46,90.29 108.71,90.54 108.71,91.35 108.25,91.81 v1(108.08,91.81)
VDDA_1P8_CSI_RX: length 26
  TOP w0.305: v1(97.45,64.95) 97.85,65.35 U9.G16
  TOP w0.381: C186.1 93.42,46.85 93.04,47.23 v1(92.46,47.23)
  TOP w0.508: C185.1 93.73,45.37 93.42,45.67 C186.1 ; C185.1 93.73,44.36 ; C185.1 93.73,44.36 ; 93.73,44.36 93.73,43.42 93.71,43.41 FL11.2 ; 93.73,44.36 93.73,44.36 ; 93.73,44.36 93.73,44.36
  L7-SIGNAL w0.127: 97.04,59.57 97.03,59.55
  L7-SIGNAL w0.152: v1(97.45,64.95) 97.04,64.54 97.04,59.57
  L7-SIGNAL w0.305: 97.03,59.55 97.03,51.81 v1(92.46,47.23)
VDDA_1P8_DP: length 7
  TOP w0.305: U9.H11 v1(102.25,65.75) ; v1(101.73,47.87) 102.23,47.87 102.69,47.4 C200.1
  TOP w0.508: C199.1 103.04,44.44 103.08,44.39 ; 103.08,44.39 103.13,44.44 103.13,45.9 C200.1 ; 103.08,44.39 103,44.3 103,42.53 FL14.2
VDDA_1P8_DSITX: length 6.3
  TOP w0.305: U9.J14 99.45,66.95 v1(99.85,66.55)
  BOTTOM w0.305: v1(101.73,47.11) 102.43,47.11 102.69,46.84 C410.1
  BOTTOM w0.508: C411.1 103.04,44.44 103.08,44.39 ; 103.08,44.39 103,44.3 103,42.53 FL28.2 ; 103.08,44.39 103.13,44.44 103.13,45.9 C410.1
VDDA_1P8_SERDES: length 2.3
  TOP w0.305: v1(99.05,78.55) 99.45,78.15 U9.AC14 ; U9.AC11 101.85,78.15 v1(102.25,78.55) ; U9.AC12 101.05,78.15 v1(101.45,78.55) ; U9.AC15 v1(98.25,78.54)
  vias: v2(99.06,99.94) v2(99.06,99.18)
VDDA_1P8_UFS: length 26.8
  TOP w0.305: U9.AC8 104.25,78.15 v1(104.65,78.55)
  L4-SIGNAL w0.152: v1(104.65,78.55) 104.65,78.79 105.05,79.19 105.05,79.51 105.29,79.76 105.62,79.76 105.85,79.99 105.85,84.12
  L4-SIGNAL w0.305: v1(107.97,98.92) 107.06,98.01 107.06,90.92 106.68,90.54 106.68,84.95 105.85,84.12
  BOTTOM w0.508: FL19.2 106.81,104.38 106.81,102.62 106.72,102.53 ; 106.72,102.53 106.67,102.48 106.67,100.67 106.77,100.57 C245.1 ; 106.72,102.53 106.77,102.48
VDDA_1P8_USB: length 29.3
  TOP w0.305: v1(103.85,78.55) 103.45,78.15 U9.AC9
  TOP w0.381: v1(107.95,99.68) 107.39,99.68 107.11,99.96 C45.1
  TOP w0.508: C46.1 106.77,102.48 106.72,102.53 ; C45.1 106.67,101.01 106.67,102.48 106.72,102.53 ; 106.72,102.53 106.81,102.62 106.81,104.38 FL4.2
  L4-SIGNAL w0.152: v1(103.85,78.55) 104.26,78.96 104.26,79.51 104.5,79.76 104.82,79.76 105.06,80 105.06,80.78 105.06,80.79 105.06,83.71
  L4-SIGNAL w0.305: 105.06,83.71 105.06,84.09 105.66,84.7 105.66,90.41 106.55,91.3 106.55,98.28 v1(107.95,99.68)
VDDA_LM5141: length 12.1
  TOP w0.203: 193.55,105.27 v2(193.55,104.45) 193.55,104.38 193.28,104.11 U1007.2 ; v2(189.99,107.05) R1028.2 R1027.2
  BOTTOM w0.305: 195.07,105.02 194.12,105.02 v2(193.55,104.45) 193.17,104.83 193.17,106.92 192.41,107.69 190.63,107.69 v2(189.99,107.05)
VDDA_TC811: length 6.2
  TOP w0.229: U2011.11 43.79,43.27 v2(43.43,42.92)
  TOP w0.305: v2(43.94,46.85) 43.94,47.41 C2037.1 43.18,47.41 v2(43.18,46.84)
  BOTTOM w0.229: C2125.1 43.81,42.53 v2(43.43,42.92)
  BOTTOM w0.305: v2(43.18,46.84) 42.93,47.09 C2128.1 ; v2(43.94,46.85) 44.2,47.11 C2129.1
VDDHS11_DSI: length 11
  TOP w0.305: 111,18.71 111,18.15 110.78,17.93 v1(110.24,17.93) ; C3068.1 v1(107.04,19.61) ; C3067.1 v1(113.94,21.52) ; C3069.1 v1(108.15,19.61)
  TOP w0.381: C3071.1 112.12,18.71 111,18.71 C3070.1
  BOTTOM w0.305: U3019.64 112.7,27.77 113.16,28.22 113.16,29 ; U3019.21 110.34,18.03 v1(110.24,17.93) ; v1(107.04,19.61) 106.83,19.41 U3019.28 ; v1(113.8,29) 113.16,29 ; 113.16,29 C3098.1 ; v1(108.15,19.61) 108.34,19.43 U3019.25 ; U3019.12 v1(113.94,21.52)
VDDI_MMC2: length 2.7
  TOP w0.305: U1017.E4 v2(157.67,87.21)
  BOTTOM w0.305: C1238.1 158.27,86.6 v2(157.67,87.21) 157.73,87.28 157.73,88.25
VDDIO_TC811: length 5.8
  TOP w0.305: v2(45.59,36.82) 45.59,36.26 C2023.1 46.35,36.26 v2(46.35,36.83) ; v2(46.74,38.09) 46.74,38.87 U2011.22
  BOTTOM w0.254: C2124.1 v2(46.74,38.09)
  BOTTOM w0.305: 45.59,36.83 v2(45.59,36.82) 45.34,36.57 C2118.1 ; C2119.1 46.61,36.58 v2(46.35,36.83)
VDDL11_DSI: length 26.1
  TOP w0.229: v1(102.23,26.31) 102.23,25.84 103.13,24.94 C3062.1
  TOP w0.305: v1(116.63,23.02) 116.7,23.09 FL3014.2
  L9-SIGNAL w0.305: v1(102.23,26.31) 104.56,23.99 112.39,23.99 113.41,22.98 116.1,22.98 116.14,23.02 v1(116.63,23.02)
  BOTTOM w0.229: C3101.1 102.69,24.78 102.72,24.75
  BOTTOM w0.305: U3019.42 103.46,24.02 102.72,24.75 102.72,25.57 102.23,26.06 v1(102.23,26.31) ; U3019.9 114.73,23.02 ; 114.73,23.02 115.87,23.02 ; 114.73,23.02 C3103.1 ; 115.87,23.02 v1(116.63,23.02) ; 115.87,23.02 C3102.1
VDDP11_DSI: length 7.2
  BOTTOM w0.305: C3096.1 104.78,29.25 ; 104.78,29.25 105.34,28.69 U3019.50 ; 104.78,29.25 103.47,29.25 103.46,29.25 ; C3097.1 103.46,29.25 ; 103.46,29.25 v1(102.74,29.25) ; 113.92,17.28 113.92,17.75 113.61,18.06 113.09,18.06 112.99,18.16 112.67,18.16 112.34,18.5 U3019.17
  BOTTOM w0.381: v1(114.64,17.28) 113.92,17.28 C3110.1
  vias: v1(119.38,26.66)
VINT_LEOA_1V8: length 3.2
  TOP w0.305: U27.2 134.07,102.2 135.29,103.43 C509.1 ; R280.1 v2(89.03,117.72)
VINT_LEOB_1V8: length 2.6
  TOP w0.305: C541.1 82.48,102.44 81.26,103.67 U29.2
AUDIO_EXT_REFCLK1/MCAN4_TX: length 55.8
  TOP w0.191: U9.AE20 v1(94.25,80.15)
  BOTTOM w0.127: v1(94.25,80.15) 94.66,80.56 94.66,83.58 94.23,84 94.23,85.59 92.33,87.49 57.53,87.49 56.77,88.25 46.99,88.25 TPX122.1
BOOT_EEPROM_WP: length 32.8
  TOP w0.229: v1(90.25,64.15) 90.25,64.15 U9.F25
  L5-PWR/GND w0.097: TPX275.1 66.8,50.28 72.39,55.87 78.36,55.87 81.91,59.43 86.84,59.43 87.49,60.08 87.49,60.29 87.7,60.5 87.91,60.5 88.29,60.88 88.29,61.09 88.5,61.3 88.71,61.3 89.09,61.68 89.09,61.89 89.3,62.1 89.51,62.1 89.89,62.48 89.89,62.7 90.1,62.9 90.31,62.9 90.61,63.2 90.61,63.79 v1(90.25,64.15)
C_AUDIO_EXT_REFCLK2: length 37.4
  TOP w0.191: U9.W26 v1(89.45,75.35)
  L5-PWR/GND w0.097: TPX182.1 54.48,74.41 69.98,74.41 70.61,73.78 80.52,73.78 80.77,74.03 84.84,74.03 85.72,74.92 89.02,74.92 v1(89.45,75.35)
C_DP0_AUX_N: length 53.8
  TOP w0.119: U9.G6 v1(106.25,64.95) ; C415.1 129.52,25.53 129.52,25.77 v1(129.29,26.01)
  L2-SIGNAL w0.076: v1(129.29,26.01) 129.57,26.29 129.57,28 114.98,42.59 114.47,42.59 105.84,51.21 105.84,57.42 104.52,58.74 104.52,59.69 104.3,59.92 104.3,64.29 104.51,64.5 104.8,64.5 104.81,64.51 105.1,64.8 105.1,65.09 105.31,65.3 105.6,65.3 105.81,65.09 105.81,64.8 105.8,64.79 105.8,64.74 105.87,64.67 105.98,64.67 v1(106.25,64.95)
C_DP0_AUX_P: length 52.1
  TOP w0.119: v1(130.05,26.01) 129.79,25.75 129.79,25.55 C414.1 ; U9.F7 v1(105.45,64.15)
  L2-SIGNAL w0.076: v1(130.05,26.01) 129.77,26.29 129.77,28.08 115.06,42.79 114.55,42.79 106.04,51.3 106.04,57.5 104.72,58.82 104.72,59.63 105.01,59.91 105.01,64.42 105.18,64.59 105.6,64.59 105.61,64.6 105.66,64.6 105.73,64.53 105.73,64.42 v1(105.45,64.15)
C_DP0_TX0_N: length 74.1
  TOP w0.119: v1(102.25,60.95) 101.85,61.35 U9.B11 ; v1(141.22,22.71) 141.46,22.47 141.46,22.23 C422.1
  L9-SIGNAL w0.076: v1(141.22,22.71) 141.48,22.45 141.48,19.92 140.24,18.68 127.23,18.68 123.44,22.47 123.44,28.95 118.36,34.03 118.36,38.09 110.87,45.58 107.7,45.58 101.67,51.61 101.67,59.86 101.81,60 101.81,60.19 101.86,60.24 101.86,60.55 v1(102.25,60.95)
C_DP0_TX0_P: length 73.8
  TOP w0.119: v1(141.99,22.71) 141.72,22.45 141.72,22.25 C423.1 ; U9.A12 v1(101.45,60.14)
  L9-SIGNAL w0.076: v1(101.45,60.14) 101.47,60.13 101.47,51.53 107.61,45.38 110.79,45.38 118.16,38.01 118.16,33.94 123.24,28.86 123.24,22.38 127.15,18.48 140.32,18.48 141.68,19.84 141.68,22.4 v1(141.99,22.71)
C_DP0_TX1_N: length 66.4
  TOP w0.119: v1(138.3,24.36) 138.54,24.12 138.54,23.88 C420.1 ; U9.B10 v1(103.05,60.95)
  L9-SIGNAL w0.076: v1(138.3,24.36) 138.58,24.08 138.58,23.89 138.61,23.86 138.61,21.92 137.2,20.51 127.85,20.51 125.17,23.19 125.17,32.76 109.05,48.88 109.05,48.89 102.66,55.28 102.66,60.34 102.78,60.46 102.78,60.67 v1(103.05,60.95)
C_DP0_TX1_P: length 66.3
  TOP w0.119: C421.1 138.8,23.9 138.8,24.1 v1(139.06,24.36) ; U9.A11 v1(102.25,60.14)
  L9-SIGNAL w0.076: v1(102.25,60.14) 102.29,60.14 102.38,60.06 102.38,59.97 102.4,59.95 102.4,59.91 102.45,59.87 102.45,55.19 108.84,48.8 124.97,32.68 124.97,23.1 127.76,20.31 137.29,20.31 138.81,21.83 138.81,23.95 138.79,23.97 138.79,24.08 v1(139.06,24.36)
C_DP0_TX2_N: length 59.1
  TOP w0.119: v1(104.65,60.95) 104.25,61.35 U9.B8 ; C418.1 135.62,22.23 135.62,22.47 v1(135.38,22.71)
  L9-SIGNAL w0.076: v1(135.38,22.71) 135.66,22.43 135.66,22.02 135.3,21.66 133.94,21.66 133.18,22.42 128.08,22.42 126.44,24.05 126.44,32.78 103.99,55.24 103.99,59.77 104.21,60 104.21,60.5 v1(104.65,60.95)
C_DP0_TX2_P: length 58.8
  TOP w0.119: v1(136.14,22.71) 135.88,22.45 135.88,22.25 C419.1 ; U9.A9 v1(103.85,60.15)
  L9-SIGNAL w0.076: v1(136.14,22.71) 135.86,22.43 135.86,21.94 135.38,21.45 133.86,21.45 133.1,22.21 127.99,22.21 126.24,23.97 126.24,32.7 103.78,55.15 103.78,60.14 103.82,60.18 v1(103.85,60.14)
C_DP0_TX3_N: length 53.3
  TOP w0.119: C416.1 132.57,23.75 132.57,23.99 v1(132.33,24.23) ; v1(105.45,60.95) 105.05,61.35 U9.B7
  L9-SIGNAL w0.076: v1(105.45,60.95) 105.18,60.67 105.18,60.46 105.03,60.31 105.03,60.06 105.12,59.97 105.12,55.4 127.51,33.01 127.51,25.04 128.99,23.56 132.5,23.56 132.61,23.67 132.61,23.95 v1(132.33,24.23)
C_DP0_TX3_P: length 53.1
  TOP w0.119: C417.1 132.83,23.77 132.83,23.97 v1(133.1,24.23) ; U9.A8 v1(104.65,60.15)
  L9-SIGNAL w0.076: v1(104.65,60.14) 104.91,59.88 104.91,55.32 127.3,32.93 127.3,24.96 128.91,23.36 132.59,23.36 132.82,23.59 132.82,23.95 v1(133.1,24.23)
C_MCASP10_ACLKR: length 39.2
  TOP w0.191: U9.Y28 v1(87.85,76.15)
  BOTTOM w0.127: TPX185.1 50.44,75.45 57.56,75.45 58.17,76.06 78.69,76.06 78.83,76.2 81.7,76.2 81.84,76.06 86.26,76.06 86.57,75.76 87.45,75.76 v1(87.85,76.15)
C_MCASP10_AFSR: length 34.7
  TOP w0.191: U9.V23 v1(91.85,74.55)
  L7-SIGNAL w0.097: TPX11.1 65.28,66.03 71.16,71.91 81.19,71.91 82.21,72.93 90.86,72.93 91.44,73.51 91.44,74.14 v1(91.85,74.55)
C_MCASP10_AXR4: length 36.4
  TOP w0.191: U9.V25 v1(90.25,74.55)
  L7-SIGNAL w0.097: v1(90.25,74.55) 89.88,74.18 85.62,74.18 85.47,74.03 78.23,74.03 76.83,75.43 60.2,75.43 TPX36.1
C_MCASP10_AXR5: length 33
  TOP w0.191: v1(88.65,75.35) 89.05,74.95 U9.W27
  L7-SIGNAL w0.097: TPX60.1 58.67,76.06 76.96,76.06 78.53,74.5 84.79,74.5 85.24,74.94 88.24,74.94 v1(88.65,75.35)
C_MCASP10_AXR6: length 37.8
  TOP w0.191: v1(87.05,75.35) 87.45,74.95 U9.W29
  L9-SIGNAL w0.097: TPX84.1 51.7,75.44 52.74,75.44 52.75,75.43 53.68,75.43 53.69,75.44 54.01,75.44 54.02,75.43 54.95,75.43 54.96,75.44 55.28,75.44 55.29,75.43 56.22,75.43 56.23,75.44 56.55,75.44 56.56,75.43 57.49,75.43 57.5,75.44 57.82,75.44 57.83,75.43 58.93,75.43 59.82,76.32 75.06,76.32 76.71,74.67 84.84,74.67 85.52,75.35 v1(87.05,75.35)
C_MCASP11_AXR4: length 35.8
  TOP w0.191: U9.Y29 87.45,75.75 v1(87.05,76.15)
  L7-SIGNAL w0.097: v1(87.05,76.15) 85.38,76.15 84.96,76.57 55.37,76.57 54.36,75.55 53.09,75.55 TPX12.1
C_MCASP11_AXR5: length 41.5
  TOP w0.191: U9.Y27 v1(88.65,76.15)
  L9-SIGNAL w0.097: v1(88.65,76.15) 88.53,76.15 88.16,75.78 85.88,75.78 85.13,76.53 59.73,76.53 58.85,75.65 49.37,75.65 TPX135.1
C_MCASP11_AXR6: length 35.8
  TOP w0.191: v1(91.05,75.35) 91.45,74.95 U9.W24
  L7-SIGNAL w0.097: TPX37.1 64.01,65.27 71.49,72.75 76.85,72.75 77.22,72.38 81.03,72.38 81.79,73.14 90.17,73.14 90.68,73.65 90.68,74.98 v1(91.05,75.35)
C_MCASP11_AXR7: length 35.4
  TOP w0.191: U9.W25 v1(90.25,75.35)
  L7-SIGNAL w0.097: TPX109.1 57.66,76.32 84.71,76.32 85.3,75.73 89.87,75.73 v1(90.25,75.35)
C_PCIE0_TX0_N: length 51.4
  TOP w0.267: U9.AF19 v1(95.05,80.95)
  L7-SIGNAL w0.145: v1(95.05,80.95) 94.81,81.19 arc(94.69,81.38) 94.64,81.6 94.64,83.34 arc(94.68,83.52) 94.78,83.67 95.22,84.11 95.21,84.11 arc(95.23,84.13) 95.26,84.15 95.26,84.15 arc(95.37,84.32) 95.41,84.51 95.41,96.28 arc(95.29,96.86) 94.96,97.36 94.92,97.39 arc(94.32,98.3) 94.11,99.37 94.11,115.14 arc(93.95,115.92) 93.51,116.58 92.21,117.89 arc(91.92,118.31) 91.82,118.82 91.82,121.5 arc(91.77,121.76) 91.62,121.98 90.08,123.52 arc(89.87,123.67) 89.62,123.72 89.43,123.72 arc(89.13,123.78) 88.88,123.94 87.09,125.73 arc(86.99,125.88) 86.96,126.06 86.96,126.72 arc(86.95,126.76) 86.93,126.8 v1(86.74,126.99)
  BOTTOM w0.188: C227.1 86.79,127.68 86.79,127.04 v1(86.74,126.99)
C_PCIE0_TX0_P: length 51.4
  TOP w0.267: U9.AG18 96.25,81.35 v1(95.85,81.75)
  L7-SIGNAL w0.145: v1(87.5,126.99) 87.28,126.77 87.27,126.75 87.27,126.06 arc(87.29,126) 87.32,125.96 89.1,124.17 arc(89.25,124.07) 89.43,124.03 89.62,124.03 arc(89.99,123.96) 90.3,123.75 91.84,122.21 arc(92.06,121.88) 92.14,121.5 92.14,118.82 arc(92.21,118.44) 92.43,118.11 93.73,116.81 arc(94.25,116.05) 94.42,115.14 94.42,99.37 arc(94.61,98.42) 95.15,97.62 95.19,97.58 arc(95.58,96.99) 95.72,96.28 95.72,84.51 arc(95.66,84.2) 95.48,83.93 arc(95.45,83.88) 95.44,83.82 95.44,81.53 arc(95.65,81.31) 95.86,81.53 95.86,81.74 v1(95.85,81.75)
  BOTTOM w0.188: C226.1 87.38,127.12 v1(87.5,126.99)
C_PCIE1_TX0_N: length 50.7
  TOP w0.267: U9.AF15 98.65,80.55 v1(98.25,80.95)
  L7-SIGNAL w0.145: v1(98.25,80.95) 98.28,80.98 arc(98.6,81.21) 98.97,81.33 arc(99,81.34) 99.02,81.34 arc(99.09,81.34) 99.16,81.35 99.28,81.35 arc(99.64,81.5) 99.8,81.87 99.8,83.55 99.97,84.63 99.97,84.98 99.97,85.94 99.97,86.48 99.97,86.76 99.97,88.6 100.3,88.93 100.3,93.54 arc(100.34,93.74) 100.45,93.92 arc(100.52,94.03) 100.55,94.15 100.55,97.82 arc(100.49,98.12) 100.32,98.38 100.09,98.6 arc(100,98.75) 99.96,98.92 99.96,99.98 arc(99.88,100.38) 99.66,100.71 98.34,102.03 arc(98.11,102.38) 98.03,102.79 98.03,117.43 98.03,117.43 98.03,117.49 98.03,117.69 97.87,121.77 arc(97.83,122.07) 97.75,122.36 97.75,122.37 97.72,122.43 97.72,122.42 arc(97.39,123.04) 96.95,123.58 95.11,125.42 arc(94.95,125.66) 94.89,125.94 94.89,126.59 arc(94.93,126.75) 95.01,126.88 v1(95.12,126.99)
  BOTTOM w0.188: v1(95.12,126.99) 95,127.12 C224.1
C_PCIE1_TX0_P: length 50.7
  TOP w0.267: U9.AG14 v1(99.05,81.75)
  L7-SIGNAL w0.145: v1(99.05,81.75) 99.28,81.75 arc(99.42,81.81) 99.48,81.95 99.48,83.58 99.65,84.66 99.65,84.98 99.65,85.94 99.65,86.48 99.65,86.76 99.65,88.73 99.98,89.06 99.98,89.99 arc(99.92,90.12) 99.79,90.18 99.58,90.18 arc(99.39,90.36) 99.58,90.55 99.79,90.55 arc(99.92,90.61) 99.98,90.74 99.98,92.13 arc(99.92,92.26) 99.79,92.31 99.68,92.31 arc(99.49,92.5) 99.68,92.69 99.79,92.69 arc(99.92,92.74) 99.98,92.87 99.98,93.6 arc(100.03,93.87) 100.18,94.1 arc(100.22,94.15) 100.23,94.22 100.23,97.82 arc(100.2,98) 100.09,98.15 99.87,98.38 arc(99.7,98.63) 99.64,98.92 99.64,99.98 arc(99.59,100.25) 99.43,100.49 98.12,101.8 arc(97.82,102.26) 97.71,102.79 97.71,117.68 97.55,121.76 arc(97.52,122.01) 97.45,122.25 arc(97.44,122.28) 97.43,122.3 97.43,122.31 arc(97.13,122.87) 96.72,123.36 94.88,125.2 arc(94.66,125.54) 94.58,125.94 94.58,126.64 arc(94.55,126.76) 94.48,126.87 v1(94.36,126.99)
  BOTTOM w0.188: C225.1 94.41,127.68 94.41,127.04 v1(94.36,126.99)
C_PCIE1_TX1_N: length 49.9
  TOP w0.267: U9.AF16 v1(97.45,80.95)
  L7-SIGNAL w0.145: v1(91.82,126.99) 91.88,126.93 arc(91.97,126.79) 92,126.63 92,125.96 arc(92.08,125.58) 92.29,125.26 95.23,122.32 arc(95.5,121.92) 95.59,121.45 95.59,118.6 arc(95.7,118.07) 96,117.62 96.31,117.31 arc(96.57,116.91) 96.66,116.45 96.66,101.64 arc(96.78,101.07) 97.1,100.58 97.51,100.17 arc(97.76,99.8) 97.85,99.35 97.85,88.1 arc(97.89,87.93) 97.99,87.78 98.05,87.71 arc(98.15,87.56) 98.19,87.39 98.19,84.05 arc(98.17,83.96) 98.12,83.89 97.98,83.75 arc(97.89,83.61) 97.86,83.45 97.86,81.85 arc(97.77,81.4) 97.51,81.01 v1(97.45,80.95)
  BOTTOM w0.188: C223.1 91.87,127.68 91.87,127.04 v1(91.82,126.99)
C_PCIE1_TX1_P: length 49.9
  TOP w0.267: v1(98.25,81.75) 98.65,81.35 U9.AG15
  L7-SIGNAL w0.145: v1(98.25,81.75) 98.29,81.75 arc(98.55,81.85) 98.65,82.11 98.65,83.57 arc(98.72,83.72) 98.87,83.78 98.89,83.78 arc(99.03,83.84) 99.09,83.98 99.09,83.98 arc(99.04,84.09) 98.92,84.14 98.65,84.14 arc(98.55,84.18) 98.51,84.28 98.51,87.39 arc(98.45,87.68) 98.28,87.94 98.21,88 arc(98.18,88.05) 98.17,88.1 98.17,99.35 arc(98.06,99.92) 97.74,100.4 97.33,100.81 arc(97.07,101.19) 96.98,101.64 96.98,116.45 arc(96.87,117.03) 96.53,117.53 96.22,117.84 arc(95.99,118.19) 95.91,118.6 95.91,121.45 arc(95.79,122.04) 95.46,122.55 92.52,125.48 arc(92.37,125.7) 92.32,125.96 92.32,126.58 arc(92.35,126.72) 92.42,126.83 v1(92.58,126.99)
  BOTTOM w0.188: v1(92.58,126.99) 92.46,127.12 C222.1
C_PCIE2_TX0_N: length 49.9
  TOP w0.267: U9.AF13 100.65,80.94 v1(100.65,80.95)
  L7-SIGNAL w0.145: v1(100.65,80.95) 100.48,81.12 arc(100.32,81.36) 100.26,81.64 100.26,83.42 arc(100.29,83.55) 100.37,83.67 101,84.31 arc(101.08,84.43) 101.11,84.57 101.11,87.69 101.07,88.17 101.03,88.59 101.03,92.94 arc(101.11,93.32) 101.32,93.65 arc(101.45,93.83) 101.49,94.05 101.49,98.75 arc(101.42,99.08) 101.23,99.36 100.98,99.62 arc(100.77,99.94) 100.69,100.31 100.69,100.69 arc(100.59,101.23) 100.28,101.68 99.33,102.64 arc(98.94,103.22) 98.81,103.9 98.81,116.7 arc(98.92,117.29) 99.25,117.79 99.29,117.82 arc(99.4,117.99) 99.44,118.19 99.44,121.78 arc(99.32,122.37) 98.99,122.87 97.59,124.26 arc(97.28,124.74) 97.16,125.3 97.16,126.54 arc(97.13,126.71) 97.03,126.86 v1(96.9,126.99)
  BOTTOM w0.188: C213.1 96.95,127.68 96.95,127.04 v1(96.9,126.99)
C_PCIE2_TX0_P: length 50
  TOP w0.267: U9.AG12 101.45,81.74 v1(101.45,81.75)
  L7-SIGNAL w0.145: v1(101.45,81.75) 101.45,81.52 arc(101.25,81.32) 101.05,81.52 101.05,83.43 arc(101.03,83.53) 100.97,83.63 arc(100.93,83.73) 100.97,83.83 101.28,84.13 arc(101.39,84.3) 101.43,84.5 101.43,84.57 101.43,87.69 101.43,87.7 101.43,87.72 101.38,88.22 101.35,88.73 101.35,92.94 arc(101.4,93.2) 101.55,93.42 arc(101.74,93.71) 101.81,94.05 101.81,98.75 arc(101.72,99.2) 101.46,99.59 101.2,99.85 arc(101.06,100.06) 101.01,100.31 101.01,100.69 arc(100.88,101.35) 100.51,101.91 99.55,102.86 arc(99.24,103.34) 99.12,103.9 99.12,116.7 arc(99.22,117.17) 99.48,117.56 99.51,117.6 arc(99.69,117.87) 99.76,118.19 99.76,121.78 arc(99.62,122.49) 99.21,123.09 97.82,124.49 arc(97.57,124.86) 97.48,125.3 97.48,126.55 arc(97.53,126.79) v1(97.66,126.99)
  BOTTOM w0.188: v1(97.66,126.99) 97.54,127.12 C212.1
C_PCIE2_TX1_N: length 49.3
  TOP w0.267: U9.AF12 101.45,80.94 v1(101.45,80.95)
  L7-SIGNAL w0.145: v1(99.44,126.99) 99.6,126.83 arc(99.68,126.72) 99.7,126.58 99.7,125.86 arc(99.79,125.43) 100.04,125.05 100.93,124.17 arc(101.19,123.77) 101.28,123.31 101.28,118.13 arc(101.38,117.62) 101.68,117.18 102.25,116.61 arc(102.42,116.36) 102.48,116.06 102.48,107.87 arc(102.54,107.53) 102.74,107.24 102.84,107.14 arc(102.97,106.95) 103.01,106.73 103.01,95.87 arc(102.96,95.62) 102.82,95.41 arc(102.71,95.24) 102.67,95.04 102.67,93.63 arc(102.72,93.36) 102.88,93.12 102.92,93.08 arc(102.96,93.02) 102.98,92.95 102.98,89.26 arc(102.95,89.12) 102.87,89 arc(102.64,88.66) 102.56,88.25 102.56,84.55 arc(102.53,84.42) 102.46,84.31 102.12,83.98 arc(101.93,83.69) 101.86,83.35 101.86,81.66 arc(101.81,81.38) 101.65,81.15 v1(101.45,80.95)
  BOTTOM w0.188: C221.1 99.49,127.68 99.49,127.04 v1(99.44,126.99)
C_PCIE2_TX1_P: length 49.3
  TOP w0.267: U9.AG11 102.25,81.74 v1(102.25,81.75)
  L7-SIGNAL w0.145: v1(100.2,126.99) 100.18,126.97 arc(100.06,126.79) 100.02,126.58 100.02,125.86 arc(100.08,125.55) 100.26,125.28 101.15,124.39 arc(101.48,123.89) 101.6,123.31 101.6,118.13 arc(101.68,117.74) 101.9,117.41 102.48,116.83 arc(102.71,116.48) 102.79,116.06 102.79,107.87 arc(102.84,107.65) 102.96,107.47 103.07,107.36 arc(103.26,107.07) 103.33,106.73 103.33,95.87 arc(103.25,95.5) 103.04,95.19 103.04,95.19 arc(103,95.12) 102.98,95.04 102.98,93.64 arc(103.02,93.48) 103.1,93.35 103.14,93.31 arc(103.25,93.14) 103.29,92.95 103.29,89.26 arc(103.24,89) 103.09,88.78 103.09,88.78 arc(102.93,88.54) 102.87,88.25 102.87,84.36 arc(102.86,84.29) 102.81,84.22 102.57,83.97 arc(102.5,83.81) 102.57,83.66 arc(102.63,83.56) 102.66,83.44 102.66,81.54 arc(102.45,81.34) 102.25,81.54 v1(102.25,81.75)
  BOTTOM w0.188: C220.1 100.08,127.12 v1(100.2,126.99)
